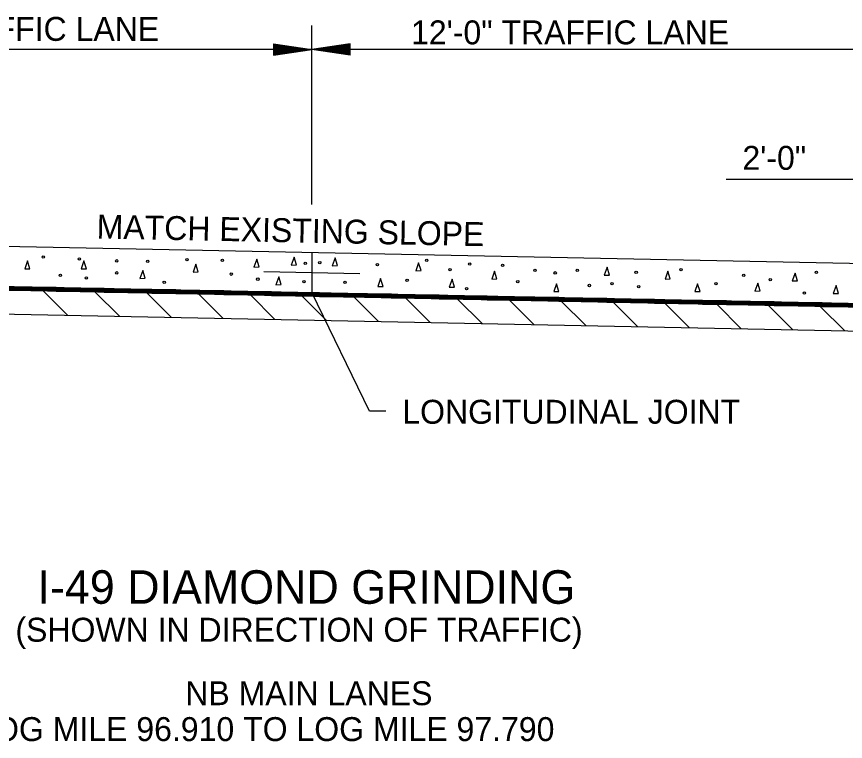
# Model space of a CAD drawing. Extents: x 60325 to 61047, y 53669 to 53767.
# Drawn here: x 60361.08 to 60378.39, y 53730.89 to 53746.03 of the extents above; entities that cross this region are included whole.
import ezdxf

# ---------------------------------------------------------------- set-up
doc = ezdxf.new("R2010")
doc.units = 0
doc.layers.add('R_Border', color=7, linetype='Continuous')
doc.layers.add('R_Border Prem', color=7, linetype='Continuous')

msp = doc.modelspace()

# ---------------------------------------------------------------- linework, layer by layer
at = {"layer": 'R_Border'}
for p, q in [((60367.247, 53742.105), (60367.247, 53745.845)), ((60367.247, 53745.345), (60355.247, 53745.345)), ((60366.447, 53745.465), (60367.247, 53745.345)), ((60366.447, 53745.465), (60366.447, 53745.225)), ((60366.447, 53745.445), (60367.113, 53745.345)), ((60366.447, 53745.424), (60366.975, 53745.345)), ((60366.447, 53745.404), (60366.842, 53745.345)), ((60366.447, 53745.383), (60366.707, 53745.345)), ((60366.447, 53745.363), (60366.573, 53745.345)), ((60366.447, 53745.225), (60367.247, 53745.345)), ((60366.447, 53745.305), (60366.707, 53745.345)), ((60366.447, 53745.265), (60366.975, 53745.345)), ((60366.447, 53745.245), (60367.113, 53745.345)), ((60366.447, 53745.285), (60366.842, 53745.345)), ((60366.447, 53745.326), (60366.573, 53745.345)), ((60368.047, 53745.465), (60367.247, 53745.345)), ((60379.247, 53745.345), (60367.247, 53745.345)), ((60368.047, 53745.225), (60367.247, 53745.345)), ((60368.047, 53745.445), (60367.38, 53745.345)), ((60368.047, 53745.245), (60367.38, 53745.345)), ((60368.047, 53745.424), (60367.518, 53745.345)), ((60368.047, 53745.265), (60367.518, 53745.345)), ((60368.047, 53745.404), (60367.651, 53745.345)), ((60368.047, 53745.285), (60367.651, 53745.345)), ((60368.047, 53745.384), (60367.787, 53745.345)), ((60368.047, 53745.306), (60367.787, 53745.345)), ((60368.047, 53745.363), (60367.92, 53745.345)), ((60368.047, 53745.326), (60367.92, 53745.345)), ((60368.047, 53745.225), (60368.047, 53745.465)), ((60375.9, 53742.639), (60379.247, 53742.639)), ((60367.247, 53741.105), (60367.247, 53740.271)), ((60366.247, 53740.708), (60367.247, 53740.688)), ((60367.247, 53740.688), (60368.246, 53740.668)), ((60368.448, 53737.791), (60367.247, 53740.271)), ((60368.795, 53737.791), (60368.448, 53737.791))]:
    msp.add_line(p, q, dxfattribs=at)
msp.add_lwpolyline([(60353.216, 53741.263), (60355.247, 53741.345), (60381.247, 53740.825)], dxfattribs=at)
at = {"layer": 'R_Border Prem'}
for p, q in [((60355.247, 53740.511), (60383.247, 53739.951)), ((60355.247, 53740.431), (60383.247, 53739.871)), ((60357.406, 53740.388), (60361.407, 53740.388)), ((60357.906, 53740.378), (60361.907, 53740.378)), ((60358.406, 53740.368), (60362.407, 53740.368)), ((60358.906, 53740.358), (60362.907, 53740.358)), ((60359.406, 53740.348), (60363.407, 53740.348)), ((60359.906, 53740.338), (60363.907, 53740.338)), ((60360.406, 53740.328), (60364.407, 53740.328)), ((60360.906, 53740.318), (60364.907, 53740.318)), ((60361.406, 53740.308), (60365.407, 53740.308)), ((60361.634, 53740.303), (60362.144, 53739.793)), ((60361.906, 53740.298), (60365.907, 53740.298)), ((60362.406, 53740.288), (60366.407, 53740.288)), ((60362.716, 53740.282), (60363.226, 53739.772)), ((60362.906, 53740.278), (60366.907, 53740.278)), ((60363.406, 53740.268), (60367.407, 53740.268)), ((60363.798, 53740.26), (60364.309, 53739.75)), ((60363.906, 53740.258), (60367.907, 53740.258)), ((60364.406, 53740.248), (60368.407, 53740.248)), ((60364.881, 53740.239), (60365.391, 53739.728)), ((60364.906, 53740.238), (60368.907, 53740.238)), ((60365.406, 53740.228), (60369.407, 53740.228)), ((60365.906, 53740.218), (60369.907, 53740.218)), ((60365.963, 53740.217), (60366.473, 53739.707)), ((60366.406, 53740.208), (60370.407, 53740.208)), ((60366.906, 53740.198), (60370.907, 53740.198)), ((60367.045, 53740.195), (60367.556, 53739.685)), ((60367.406, 53740.188), (60371.407, 53740.188)), ((60367.906, 53740.178), (60371.907, 53740.178)), ((60368.128, 53740.174), (60368.638, 53739.663)), ((60368.406, 53740.168), (60372.407, 53740.168)), ((60368.906, 53740.158), (60372.907, 53740.158)), ((60369.21, 53740.152), (60369.72, 53739.642)), ((60369.406, 53740.148), (60373.407, 53740.148)), ((60369.906, 53740.138), (60373.907, 53740.138)), ((60370.292, 53740.13), (60370.803, 53739.62)), ((60370.406, 53740.128), (60374.407, 53740.128)), ((60370.906, 53740.118), (60374.907, 53740.118)), ((60371.375, 53740.109), (60371.885, 53739.598)), ((60371.406, 53740.108), (60375.407, 53740.108)), ((60355.247, 53739.931), (60397.793, 53739.08)), ((60371.906, 53740.098), (60375.907, 53740.098)), ((60372.406, 53740.088), (60376.407, 53740.088)), ((60372.457, 53740.087), (60372.967, 53739.577)), ((60372.906, 53740.078), (60376.907, 53740.078)), ((60373.406, 53740.068), (60377.407, 53740.068)), ((60373.539, 53740.065), (60374.049, 53739.555)), ((60373.906, 53740.058), (60377.907, 53740.058)), ((60374.406, 53740.048), (60378.407, 53740.048)), ((60374.621, 53740.044), (60375.132, 53739.533)), ((60374.906, 53740.038), (60378.907, 53740.038)), ((60375.406, 53740.028), (60379.407, 53740.028)), ((60375.704, 53740.022), (60376.214, 53739.512)), ((60375.906, 53740.018), (60379.907, 53740.018)), ((60376.406, 53740.008), (60380.407, 53740.008)), ((60376.786, 53740), (60377.296, 53739.49)), ((60376.906, 53739.998), (60380.907, 53739.998)), ((60377.406, 53739.988), (60381.407, 53739.988)), ((60377.868, 53739.979), (60378.379, 53739.468)), ((60377.906, 53739.978), (60381.907, 53739.978))]:
    msp.add_line(p, q, dxfattribs=at)
for points in [[(60366.874, 53741.007), (60366.813, 53740.841), (60366.923, 53740.845), (60366.874, 53741.007)], [(60367.733, 53740.994), (60367.672, 53740.828), (60367.782, 53740.832), (60367.733, 53740.994)], [(60361.31, 53740.928), (60361.249, 53740.762), (60361.359, 53740.766), (60361.31, 53740.928)], [(60362.486, 53740.928), (60362.426, 53740.762), (60362.536, 53740.766), (60362.486, 53740.928)], [(60364.825, 53740.862), (60364.765, 53740.696), (60364.875, 53740.7), (60364.825, 53740.862)], [(60366.094, 53740.967), (60366.033, 53740.801), (60366.143, 53740.806), (60366.094, 53740.967)], [(60369.477, 53740.888), (60369.417, 53740.722), (60369.527, 53740.726), (60369.477, 53740.888)], [(60363.715, 53740.729), (60363.655, 53740.563), (60363.765, 53740.568), (60363.715, 53740.729)], [(60371.063, 53740.716), (60371.003, 53740.55), (60371.113, 53740.555), (60371.063, 53740.716)], [(60373.416, 53740.795), (60373.355, 53740.629), (60373.465, 53740.634), (60373.416, 53740.795)], [(60374.684, 53740.716), (60374.624, 53740.55), (60374.734, 53740.555), (60374.684, 53740.716)], [(60377.341, 53740.676), (60377.28, 53740.51), (60377.39, 53740.515), (60377.341, 53740.676)], [(60366.556, 53740.597), (60366.496, 53740.431), (60366.606, 53740.436), (60366.556, 53740.597)], [(60368.684, 53740.558), (60368.624, 53740.392), (60368.734, 53740.396), (60368.684, 53740.558)], [(60370.178, 53740.544), (60370.117, 53740.378), (60370.227, 53740.383), (60370.178, 53740.544)], [(60372.358, 53740.452), (60372.298, 53740.286), (60372.408, 53740.29), (60372.358, 53740.452)], [(60375.305, 53740.452), (60375.245, 53740.286), (60375.355, 53740.29), (60375.305, 53740.452)], [(60376.561, 53740.465), (60376.5, 53740.299), (60376.61, 53740.304), (60376.561, 53740.465)], [(60378.2, 53740.412), (60378.139, 53740.246), (60378.249, 53740.251), (60378.2, 53740.412)]]:
    msp.add_lwpolyline(points, dxfattribs=at)
for centre in [(60361.637, 53741.009), (60362.391, 53740.97), (60364.637, 53740.956), (60363.17, 53740.93), (60363.818, 53740.917), (60365.377, 53740.943), (60367.109, 53740.877), (60367.413, 53740.89), (60368.615, 53740.851), (60369.646, 53740.943), (60370.545, 53740.864), (60371.232, 53740.838), (60361.994, 53740.626), (60363.17, 53740.679), (60365.563, 53740.652), (60370.135, 53740.745), (60371.906, 53740.732), (60372.329, 53740.679), (60372.792, 53740.732), (60374.021, 53740.692), (60374.959, 53740.745), (60376.267, 53740.626), (60377.787, 53740.692), (60362.536, 53740.573), (60364.162, 53740.481), (60366.118, 53740.547), (60367.082, 53740.494), (60367.941, 53740.481), (60369.237, 53740.52), (60371.549, 53740.494), (60373.518, 53740.454), (60375.686, 53740.454), (60376.822, 53740.534), (60370.479, 53740.349), (60373.043, 53740.415), (60374.074, 53740.388), (60377.536, 53740.256)]:
    msp.add_circle(centre, 0.025, dxfattribs=at)

# ---------------------------------------------------------------- texts
at = {"layer": 'R_Border'}
for s, height, p in [('12\'-0" TRAFFIC LANE', 0.5, (60357.414, 53745.527)), ('12\'-0" TRAFFIC LANE', 0.5, (60369.319, 53745.454)), ('2\'-0"', 0.5, (60376.241, 53742.832)), ('LONGITUDINAL JOINT', 0.5, (60369.136, 53737.526)), ('I-49 DIAMOND GRINDING', 0.7, (60361.516, 53733.764)), ('(SHOWN IN DIRECTION OF TRAFFIC)', 0.5, (60361.054, 53732.972)), ('NB MAIN LANES', 0.5, (60364.602, 53731.645)), ('LOG MILE 96.910 TO LOG MILE 97.790', 0.5, (60360.236, 53730.895))]:
    msp.add_text(s, height=height, dxfattribs=at).set_placement(p)
msp.add_text('MATCH EXISTING SLOPE', height=0.5, rotation=358.8542, dxfattribs=at).set_placement((60362.748, 53741.398))

doc.saveas('drawing.dxf')
